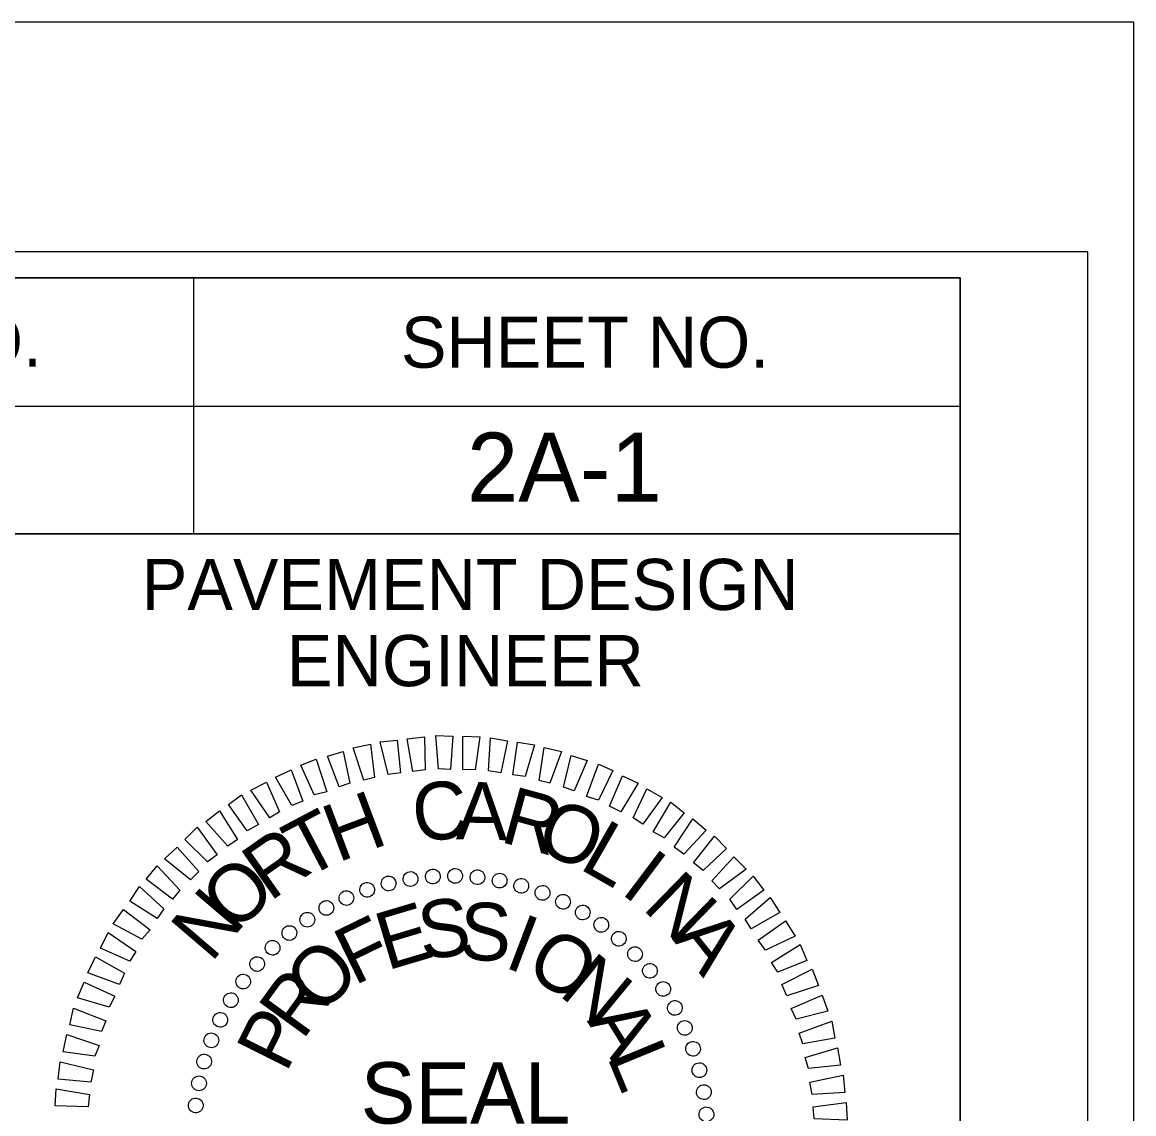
# Model space of a CAD drawing. Extents: x 3025871 to 3026431, y 707165 to 707825.
# Drawn here: x 3026258.31 to 3026274.62, y 707719.32 to 707735.34 of the extents above; entities that cross this region are included whole.
import ezdxf

# ---------------------------------------------------------------- set-up
doc = ezdxf.new("R2010")
doc.units = 0
for name, color, linetype in [('Old_Level_39', 7, 'Continuous'), ('Sheet Block Title CELL', 7, 'Continuous'), ('Sheet Cutting Line CELL', 7, 'Continuous'), ('Sheet Sticker Exception Certification CELL', 7, 'Continuous'), ('Typical Terminator CELL', 7, 'Continuous')]:
    doc.layers.add(name, color=color, linetype=linetype)

msp = doc.modelspace()

# ---------------------------------------------------------------- linework, layer by layer
at = {"layer": 'Old_Level_39'}
msp.add_lwpolyline([(3026273.948, 707731.968), (3026023.973, 707731.968), (3026023.973, 707573.703), (3026273.948, 707573.703)], close=True, dxfattribs=at)
at = {"layer": 'Sheet Block Title CELL'}
for p, q in [((3026264.013, 707722.76), (3026264.013, 707722.76)), ((3026264.336, 707722.805), (3026264.336, 707722.805)), ((3026264.666, 707722.812), (3026264.666, 707722.812)), ((3026264.996, 707722.79), (3026264.996, 707722.79)), ((3026265.318, 707722.737), (3026265.318, 707722.737)), ((3026263.368, 707722.61), (3026263.368, 707722.61)), ((3026263.683, 707722.7), (3026263.683, 707722.7)), ((3026265.633, 707722.67), (3026265.633, 707722.67)), ((3026265.948, 707722.565), (3026265.948, 707722.565)), ((3026263.068, 707722.49), (3026263.068, 707722.49)), ((3026266.248, 707722.43), (3026266.248, 707722.43)), ((3026262.776, 707722.34), (3026262.776, 707722.34)), ((3026266.541, 707722.28), (3026266.541, 707722.28)), ((3026262.491, 707722.167), (3026262.491, 707722.167)), ((3026266.811, 707722.092), (3026266.811, 707722.092)), ((3026262.228, 707721.98), (3026262.228, 707721.98)), ((3026261.981, 707721.755), (3026261.981, 707721.755)), ((3026267.073, 707721.89), (3026267.073, 707721.89)), ((3026267.306, 707721.665), (3026267.306, 707721.665)), ((3026261.756, 707721.522), (3026261.756, 707721.522)), ((3026267.531, 707721.417), (3026267.531, 707721.417)), ((3026261.553, 707721.26), (3026261.553, 707721.26)), ((3026267.718, 707721.155), (3026267.718, 707721.155)), ((3026261.366, 707720.99), (3026261.366, 707720.99)), ((3026267.891, 707720.87), (3026267.891, 707720.87)), ((3026261.216, 707720.697), (3026261.216, 707720.697)), ((3026268.041, 707720.577), (3026268.041, 707720.577)), ((3026261.081, 707720.397), (3026261.081, 707720.397)), ((3026268.161, 707720.277), (3026268.161, 707720.277)), ((3026260.976, 707720.082), (3026260.976, 707720.082)), ((3026268.251, 707719.962), (3026268.251, 707719.962)), ((3026260.908, 707719.767), (3026260.908, 707719.767)), ((3026268.311, 707719.632), (3026268.311, 707719.632)), ((3026260.856, 707719.445), (3026260.856, 707719.445))]:
    msp.add_line(p, q, dxfattribs=at)
for points in [[(3026264.043, 707724.342), (3026263.961, 707724.822), (3026264.216, 707724.852), (3026264.223, 707724.365)], [(3026264.418, 707724.38), (3026264.381, 707724.867), (3026264.628, 707724.86), (3026264.598, 707724.372)], [(3026264.778, 707724.372), (3026264.778, 707724.86), (3026265.026, 707724.852), (3026264.958, 707724.365)], [(3026263.323, 707724.215), (3026263.166, 707724.687), (3026263.421, 707724.74), (3026263.481, 707724.252)], [(3026263.683, 707724.297), (3026263.563, 707724.777), (3026263.811, 707724.8), (3026263.863, 707724.32)], [(3026265.153, 707724.35), (3026265.183, 707724.837), (3026265.431, 707724.792), (3026265.333, 707724.32)], [(3026265.513, 707724.29), (3026265.581, 707724.77), (3026265.828, 707724.732), (3026265.693, 707724.267)], [(3026265.896, 707724.207), (3026265.971, 707724.695), (3026266.226, 707724.635), (3026266.053, 707724.17)], [(3026262.596, 707723.997), (3026262.401, 707724.432), (3026262.626, 707724.522), (3026262.783, 707724.042)], [(3026262.963, 707724.117), (3026262.791, 707724.567), (3026263.023, 707724.635), (3026263.121, 707724.17)], [(3026266.256, 707724.11), (3026266.368, 707724.575), (3026266.601, 707724.5), (3026266.413, 707724.057)], [(3026262.266, 707723.84), (3026262.026, 707724.26), (3026262.258, 707724.365), (3026262.431, 707723.907)], [(3026266.593, 707723.975), (3026266.766, 707724.447), (3026266.976, 707724.357), (3026266.766, 707723.922)], [(3026266.931, 707723.832), (3026267.118, 707724.275), (3026267.351, 707724.17), (3026267.096, 707723.75)], [(3026261.943, 707723.66), (3026261.666, 707724.065), (3026261.898, 707724.185), (3026262.086, 707723.75)], [(3026267.276, 707723.66), (3026267.478, 707724.087), (3026267.703, 707723.96), (3026267.418, 707723.57)], [(3026261.613, 707723.472), (3026261.336, 707723.855), (3026261.531, 707723.997), (3026261.778, 707723.562)], [(3026267.568, 707723.457), (3026267.831, 707723.892), (3026268.026, 707723.735), (3026267.733, 707723.367)], [(3026261.328, 707723.247), (3026261.006, 707723.607), (3026261.208, 707723.765), (3026261.471, 707723.345)], [(3026267.876, 707723.232), (3026268.153, 707723.645), (3026268.348, 707723.48), (3026268.018, 707723.127)], [(3026261.028, 707723.015), (3026260.698, 707723.345), (3026260.878, 707723.525), (3026261.171, 707723.12)], [(3026268.161, 707723), (3026268.468, 707723.39), (3026268.648, 707723.21), (3026268.303, 707722.887)], [(3026260.781, 707722.752), (3026260.398, 707723.06), (3026260.586, 707723.232), (3026260.901, 707722.872)], [(3026268.431, 707722.737), (3026268.753, 707723.09), (3026268.933, 707722.91), (3026268.543, 707722.617)], [(3026260.518, 707722.467), (3026260.128, 707722.76), (3026260.293, 707722.955), (3026260.623, 707722.602)], [(3026268.693, 707722.467), (3026269.038, 707722.805), (3026269.196, 707722.602), (3026268.798, 707722.317)], [(3026260.293, 707722.182), (3026259.888, 707722.437), (3026260.031, 707722.655), (3026260.391, 707722.325)], [(3026268.918, 707722.175), (3026269.286, 707722.49), (3026269.428, 707722.272), (3026269.008, 707722.032)], [(3026260.068, 707721.882), (3026259.648, 707722.107), (3026259.798, 707722.317), (3026260.188, 707722.017)], [(3026269.113, 707721.867), (3026269.511, 707722.152), (3026269.653, 707721.927), (3026269.218, 707721.717)], [(3026259.888, 707721.56), (3026259.461, 707721.747), (3026259.573, 707721.98), (3026259.978, 707721.702)], [(3026269.308, 707721.537), (3026269.728, 707721.8), (3026269.826, 707721.567), (3026269.398, 707721.395)], [(3026259.738, 707721.215), (3026259.273, 707721.387), (3026259.386, 707721.62), (3026259.813, 707721.38)], [(3026269.458, 707721.215), (3026269.901, 707721.44), (3026269.998, 707721.2), (3026269.533, 707721.05)], [(3026259.588, 707720.885), (3026259.123, 707721.02), (3026259.221, 707721.252), (3026259.671, 707721.042)], [(3026269.593, 707720.862), (3026270.051, 707721.057), (3026270.133, 707720.825), (3026269.668, 707720.705)], [(3026259.476, 707720.525), (3026259.011, 707720.622), (3026259.063, 707720.87), (3026259.536, 707720.682)], [(3026269.713, 707720.502), (3026270.193, 707720.675), (3026270.238, 707720.427), (3026269.766, 707720.345)], [(3026259.378, 707720.165), (3026258.913, 707720.225), (3026258.966, 707720.48), (3026259.438, 707720.322)], [(3026269.803, 707720.142), (3026270.276, 707720.285), (3026270.321, 707720.03), (3026269.848, 707719.985)], [(3026259.318, 707719.782), (3026258.838, 707719.827), (3026258.868, 707720.082), (3026259.356, 707719.962)], [(3026269.871, 707719.782), (3026270.358, 707719.887), (3026270.381, 707719.632), (3026269.901, 707719.602)], [(3026259.281, 707719.422), (3026258.793, 707719.437), (3026258.808, 707719.685), (3026259.296, 707719.602)], [(3026269.916, 707719.422), (3026270.403, 707719.482), (3026270.418, 707719.227), (3026269.931, 707719.242)]]:
    msp.add_lwpolyline(points, close=True, dxfattribs=at)
for centre, major_axis in [((3026264.336, 707722.8), (-0.008, 0.108)), ((3026264.664, 707722.809), (0.002, 0.108)), ((3026264.991, 707722.789), (0.011, 0.107)), ((3026263.373, 707722.605), (-0.035, 0.102)), ((3026263.688, 707722.698), (-0.026, 0.105)), ((3026264.01, 707722.763), (-0.017, 0.107)), ((3026265.316, 707722.74), (0.021, 0.106)), ((3026265.635, 707722.664), (0.03, 0.104)), ((3026263.068, 707722.484), (-0.0439, 0.0987)), ((3026265.946, 707722.56), (0.039, 0.101)), ((3026262.774, 707722.338), (-0.0524, 0.0945)), ((3026266.247, 707722.429), (0.0473, 0.0971)), ((3026266.536, 707722.272), (0.0556, 0.0926)), ((3026262.495, 707722.166), (-0.0604, 0.0895)), ((3026262.231, 707721.971), (-0.068, 0.0839)), ((3026266.809, 707722.091), (0.0635, 0.0874)), ((3026267.066, 707721.887), (0.0709, 0.0815)), ((3026261.985, 707721.754), (-0.075, 0.0777)), ((3026267.304, 707721.661), (0.0777, 0.075)), ((3026261.759, 707721.516), (-0.0815, 0.0709)), ((3026267.522, 707721.415), (0.0839, 0.068)), ((3026261.555, 707721.259), (-0.0874, 0.0635)), ((3026267.717, 707721.151), (0.0895, 0.0604)), ((3026261.374, 707720.985), (-0.0926, 0.0556)), ((3026267.889, 707720.871), (0.0945, 0.0524)), ((3026261.217, 707720.697), (-0.0971, 0.0473)), ((3026268.035, 707720.578), (0.0987, 0.0439)), ((3026261.086, 707720.396), (-0.101, 0.039)), ((3026268.155, 707720.272), (0.102, 0.035)), ((3026260.982, 707720.084), (-0.104, 0.03)), ((3026268.248, 707719.958), (0.105, 0.026)), ((3026260.905, 707719.765), (-0.106, 0.021)), ((3026268.314, 707719.636), (0.107, 0.017)), ((3026260.857, 707719.441), (-0.107, 0.011)), ((3026268.351, 707719.31), (0.108, 0.008))]:
    msp.add_ellipse(centre, major_axis=major_axis, ratio=0.999708, dxfattribs=at)
at = {"layer": 'Sheet Cutting Line CELL'}
for p, q in [((3026260.823, 707731.578), (3026260.823, 707727.828)), ((3026242.065, 707729.703), (3026272.073, 707729.703))]:
    msp.add_line(p, q, dxfattribs=at)
for points in [[(3026272.073, 707731.586), (3026047.073, 707731.586), (3026047.073, 707574.086), (3026272.073, 707574.086)], [(3026242.065, 707731.586), (3026272.073, 707731.586), (3026272.073, 707727.828), (3026242.065, 707727.828)], [(3026257.073, 707727.828), (3026272.073, 707727.828), (3026272.073, 707710.953), (3026257.073, 707710.953)]]:
    msp.add_lwpolyline(points, close=True, dxfattribs=at)
at = {"layer": 'Typical Terminator CELL'}
msp.add_lwpolyline([(3026274.623, 707735.336), (3026022.023, 707735.336), (3026022.023, 707570.336), (3026274.623, 707570.336)], close=True, dxfattribs=at)

# ---------------------------------------------------------------- texts
at = {"layer": 'Sheet Block Title CELL'}
for s, height, rotation, p in [('C', 0.846, 6.2199, (3026264.081, 707723.3)), ('H', 0.846, 20.6195, (3026262.941, 707723)), ('A', 0.846, 359.0203, (3026264.673, 707723.345)), ('R', 0.846, 344.6211, (3026265.303, 707723.315)), ('O', 0.846, 337.4212, (3026265.806, 707723.202)), ('T', 0.846, 27.8198, (3026262.453, 707722.752)), ('L', 0.846, 330.2209, (3026266.466, 707722.925)), ('R', 0.846, 35.0205, (3026261.943, 707722.422)), ('I', 0.846, 323.0201, (3026267.073, 707722.565)), ('O', 0.846, 42.2217, (3026261.426, 707721.957)), ('N', 0.846, 315.8189, (3026267.396, 707722.332)), ('N', 0.846, 49.4235, (3026261.081, 707721.522)), ('E', 0.846, 16.6111, (3026263.661, 707721.417)), ('S', 0.846, 7.2556, (3026264.178, 707721.575)), ('S', 0.846, 357.9004, (3026264.718, 707721.582)), ('F', 0.846, 25.967, (3026263.181, 707721.192)), ('I', 0.846, 339.1896, (3026265.363, 707721.477)), ('A', 0.846, 308.6172, (3026267.838, 707721.89)), ('O', 0.846, 329.8335, (3026265.663, 707721.372)), ('O', 0.846, 44.6812, (3026262.686, 707720.75)), ('N', 0.846, 320.4766, (3026266.166, 707721.072)), ('R', 0.846, 54.0397, (3026262.423, 707720.382)), ('P', 0.846, 63.3989, (3026262.183, 707719.902)), ('A', 0.846, 301.7603, (3026266.593, 707720.682)), ('L', 0.846, 292.4008, (3026266.886, 707720.165)), ('SEAL', 0.8997, 360, (3026263.278, 707719.175))]:
    msp.add_text(s, height=height, rotation=rotation, dxfattribs=at).set_placement(p)
at = {"layer": 'Sheet Cutting Line CELL'}
for s, height, p in [('PROJECT REFERENCE NO.', 0.75001, (3026245.395, 707730.281)), ('SHEET NO.', 0.75, (3026263.868, 707730.266)), ('PAVEMENT DESIGN', 0.75001, (3026260.065, 707726.711)), ('ENGINEER', 0.75, (3026262.195, 707725.593))]:
    msp.add_text(s, height=height, rotation=360, dxfattribs=at).set_placement(p)
at = {"layer": 'Sheet Sticker Exception Certification CELL'}
msp.add_text('2A-1', height=1.0125, rotation=360, dxfattribs=at).set_placement((3026264.837, 707728.301))

doc.saveas('drawing.dxf')
